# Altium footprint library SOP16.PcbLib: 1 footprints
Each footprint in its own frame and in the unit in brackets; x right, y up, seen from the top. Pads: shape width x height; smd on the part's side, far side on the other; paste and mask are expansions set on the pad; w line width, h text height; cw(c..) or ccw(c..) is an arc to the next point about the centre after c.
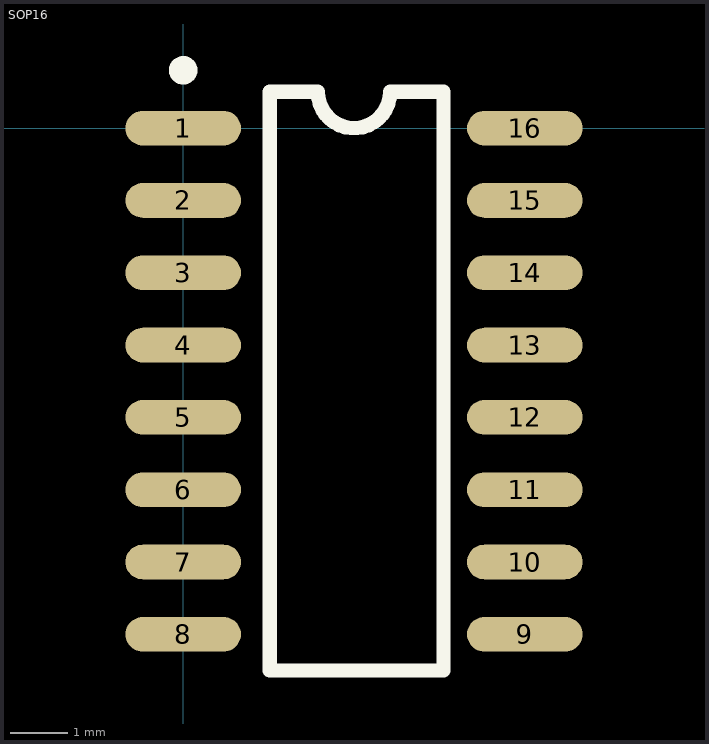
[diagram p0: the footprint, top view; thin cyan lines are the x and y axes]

## SOP16 [mil]
pads (16):
  oval 80x24 smd: 1(0,0) 2(0,-50) 3(0,-100) 4(0,-150) 5(0,-200) 6(0,-250) 7(0,-300) 8(0,-350) 9(236.22,-350) 10(236.22,-300) 11(236.22,-250) 12(236.22,-200) 13(236.22,-150) 14(236.22,-100) 15(236.22,-50) 16(236.22,0)
Top Overlay:
  circle w9.84: c0,40 r4.92
  lines w10: 60,-375 180,-375 180,25 143.11,25 cw(c118.11,25) 93.11,25 60,25 60,-375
